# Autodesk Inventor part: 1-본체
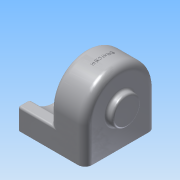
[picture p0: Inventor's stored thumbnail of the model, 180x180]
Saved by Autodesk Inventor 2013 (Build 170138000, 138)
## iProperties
Created: 2015-02
Part Number: 1-본체
Material: 알루미늄 6061
Document SubType Name: Modeling
Designer: Administrator
Density: 2.40731 g/cm^3
Mass: 511.244 g
Surface Area: 706.56 cm^2
Volume: 212.371 cm^3
Author: Administrator
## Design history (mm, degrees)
sketch "스케치1"
  geometry: L1 (47.5, -50)-(-47.5, -50); L2 (-47.5, -50)-(-47.5, 50); L3 (-47.5, 50)-(47.5, 50); L4 (47.5, 50)-(47.5, -50); L5 (47.5, -50)-(-47.5, 50); L6 (-47.5, -50)-(47.5, 50); 1 further point
  constraints: 12 end point, 2 midpoint, 2 parallel, 1 horizontal, 1 perpendicular
  dimensions: "d0" = 95 distance of L2.end L3.end; "d2" = 100 distance of L1.end L2.end
extrude "돌출1" new body sketch "스케치1" distance "d3" = 30; taper "d4" = 0 deg
sketch "스케치2"
  geometry: L1 (0, 100)-(0, 0) reference; L2 (0, 100)-(-30, 100) reference; L3 (-30, 0)-(-30, 100) reference; L4 (0, 0)-(-30, 0) reference; L5 (-50, 100)-(0, 100); L6 (0, 0)-(-50, 0); L7 (0, 0)-(0, 100); A1 r 50 centre (-50, 50) between (-50, 100) and (-50, 0); 2 further points
  constraints: 6 end point, 2 point on circle, 2 tangent, 1 centre point, 1 horizontal alignment, 1 midpoint
  dimensions: "d5" = 100 diameter of A1; "d7" = 50 distance from line of L1 A1.centre
extrude "돌출2" join sketch "스케치2" distance "d8" = 50; taper "d9" = 0 deg
sketch "스케치3"
  geometry: C1 r 40 at (50, 50); A1 r 50 centre (50, 50) between (50, 0) and (50, 100) reference; 1 further point
  constraints: 1 centre point, 1 coincident
  dimensions: "d10" = 80 diameter of C1
extrude "돌출3" cut sketch "스케치3" stored distance "d13" = 50; taper "d14" = 0 deg
sketch "스케치4"
  geometry: C1 r 25 at (50, 50); A1 r 40 centre (50, 50) between (30, 84.641) and (30, 15.359) reference; 1 further point
  constraints: 1 centre point, 1 coincident
  dimensions: "d15" = 50 diameter of C1
extrude "돌출4" join sketch "스케치4" distance "d17" = 10; taper "d18" = -20 deg
sketch "스케치5"
  geometry: C1 r 20 at (-50, 50); A1 r 50 centre (-50, 50) between (-50, 100) and (-50, 0) reference; 1 further point
  constraints: 1 centre point, 1 coincident
  dimensions: "d19" = 40 diameter of C1
extrude "돌출5" join sketch "스케치5" distance "d21" = 9; taper "d22" = 0 deg
node "작업 평면1"
sketch "스케치6"
  geometry: L1 (50, 100)-(30, 100) reference; L2 (0, 100)-(30, 100) reference; L3 (30, 0)-(50, 0) reference; L4 (0, 0)-(30, 0) reference; L5 (0, 96)-(30, 96); L6 (30, 96)-(50, 96); L7 (50, 4)-(30, 4); L8 (30, 4)-(0, 4); L9 (0, 96)-(0, 4); L10 (0, 0)-(0, 100) reference; A1 r 50 centre (50, 50) between (50, 0) and (50, 100) reference; A2 r 46 centre (50, 50) between (50, 4) and (50, 96); 2 further points
  constraints: 10 end point, 2 point on circle, 1 centre point, 1 midpoint, 1 perpendicular, 1 vertical alignment, 4 other
  dimensions: "d24" = 4 radial gap between concentric circles of A1 A2
extrude "돌출6" cut sketch "스케치6" distance "d25" = 42; taper "d26" = 0 deg
hole "구멍1" diameter "d29" = 20; stored, may be unused: countersink angle "d33" = 90 deg, drill point angle "d35" = 0 deg; dims "d30" = 6, "d31" = 28, "d32" = 10, "d34" = 14, "d45" = 10, "d46" = 10
hole "구멍2" diameter "d38" = 20; stored, may be unused: countersink angle "d42" = 90 deg, drill point angle "d44" = 0 deg; dims "d36" = 10, "d37" = 10, "d39" = 6, "d40" = 28, "d41" = 8, "d43" = 10
sketch "스케치7"
  geometry: C1 r 14 at (0, 0) reference; C2 r 21.36 at (0, 0) reference; A1 r 18 centre (0, 0) between (-18, 0) and (18, 0); 3 further points
  constraints: 4 point on circle, 2 horizontal alignment, 2 vertical alignment, 1 centre point, 1 coincident
  dimensions: "d47" = 36 diameter of A1
hole "구멍3" sketch "스케치7" at (-18, 0), (18, 0), (0, 18), (0, -18) diameter "d49" = 2.459; stored, may be unused: countersink angle "d53" = 90 deg, drill point angle "d55" = 118 deg; dims "d50" = 6, "d51" = 28, "d52" = 8, "d54" = 9
sketch "스케치8"
  geometry: L1 (47.5, -50)-(47.5, 50) reference; L2 (38.5, -41.75)-(5.5, -41.75); L3 (5.5, -41.75)-(5.5, 41.75); L4 (5.5, 41.75)-(38.5, 41.75); L5 (38.5, 41.75)-(38.5, -41.75); L6 (38.5, -41.75)-(5.5, 41.75); L7 (5.5, -41.75)-(38.5, 41.75); 7 further points
  constraints: 12 end point, 4 coincident, 3 midpoint, 2 parallel, 1 horizontal, 1 horizontal alignment, 1 perpendicular
  dimensions: "d56" = 33 distance of L3.end L4.end; "d58" = 9 distance between parallel lines of L1 L5; "d59" = 83.5 distance of L4.end L2.start
hole "구멍4" sketch "스케치8" at (5.5, 41.75), (38.5, 41.75), (38.5, -41.75), (5.5, -41.75) diameter "d60" = 5.134; stored, may be unused: countersink angle "d64" = 90 deg, drill point angle "d66" = 118 deg; dims "d61" = 10, "d62" = 28, "d63" = 8, "d65" = 13
fillet "모깎기1" dims "d67" = 10, "d68" = 6, "d69" = 0.3, "d70" = 3
fillet "모깎기2" dims "d71" = 3
chamfer "모따기1" distance "d72" = 1; stored, may be unused: second distance "d73" = 2, angle "d74" = 45 deg
node "작업 평면2"
sketch "스케치9"
  geometry: L1 (0, 40)-(0, -40) reference; 2 further points
  constraints: 1 horizontal alignment, 1 other
  dimensions: "d75" = 25 distance from line of L1 point (-25, 0)
feature "엠보싱1" sketch "스케치9" dims "d76" = 0.5, "d77" = 0
node "솔리드1"
other parameters: "d23" = -4
